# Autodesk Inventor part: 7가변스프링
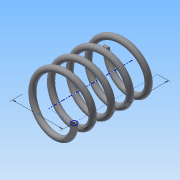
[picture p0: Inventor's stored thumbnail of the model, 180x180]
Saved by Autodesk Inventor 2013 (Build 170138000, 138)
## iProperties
Created: 2015-03
Part Number: 7가변스프링
Material: 강철, 탄소
Document SubType Name: Modeling
Designer: Administrator
Density: 7.87 g/cm^3
Mass: 48.2733 g
Surface Area: 62.0009 cm^2
Volume: 6.13383 cm^3
Author: Administrator
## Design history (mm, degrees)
sketch "스케치1"
  geometry: L1 (0, 0)-(17.5, 0); L2 (17.5, 0)-(17.5, 43.5); L3 (17.5, 43.5)-(0, 43.5); L4 (0, 43.5)-(0, 0); C1 r 2 at (17.5, 0)
  constraints: 8 end point, 2 parallel, 1 centre point, 1 coincident, 1 horizontal, 1 perpendicular
  dimensions: "d0" = 43.5 distance of L1.end L2.end (derived); "d2" = 35 diameter of L2 L4; "d3" = 4 diameter of C1
feature "코일1" sketch "스케치1" pitch "d4" = 10; turns "d6" = 4.5; dims "d5" = 43.5 (= d0), "d7" = 0, angle "d8" = 90 deg, angle "d9" = 90 deg, "d10" = 0, "d11" = 0
sketch "스케치2"
  geometry: L1 (-19.5, 0)-(-15.5, 0) reference; 1 further point
  constraints: 1 horizontal alignment
extrude "돌출1" cut sketch "스케치2" stored distance "d12" = 10; taper "d13" = 0 deg
node "작업 평면1"
sketch "스케치3"
  geometry: L1 (-19.5, 0)-(-15.5, 0) reference; 1 further point
  constraints: 1 horizontal alignment
extrude "돌출2" cut sketch "스케치3" stored distance "d15" = 10; taper "d16" = 0 deg
node "솔리드1"
node "절단 모서리 투영1"
node "절단 모서리 투영2"
other parameters: "d14" = -43.5 (= -d0)
